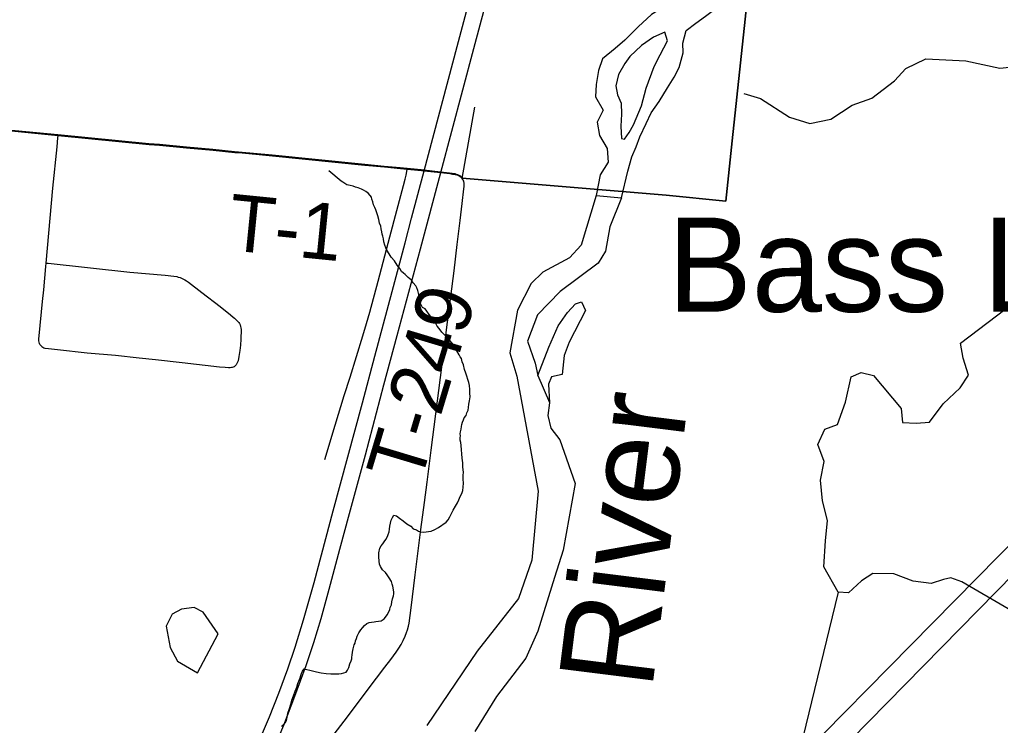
# Model space of a CAD drawing. Extents: x 0 to 34, y 0 to 22.
# Drawn here: x 23.47 to 24.456, y 18.35 to 19.059 of the extents above; entities that cross this region are included whole.
import ezdxf

# ---------------------------------------------------------------- set-up
doc = ezdxf.new("R2010")
doc.units = 0
for name, color, linetype in [('GM_X_City_Street', 7, 'Continuous'), ('GM_X_Major_River', 7, 'Continuous'), ('GM_X_Major_River_Text', 7, 'Continuous'), ('GM_X_Minor_Lake', 7, 'Continuous'), ('GM_X_Minor_Lake_Text', 7, 'Continuous'), ('GM_X_Minor_River', 7, 'Continuous'), ('GM_X_Rail_Line', 7, 'Continuous'), ('GM_X_State_Route', 7, 'Continuous'), ('GM_X_Township_Road', 7, 'Continuous'), ('GM_X_Township_Road_Text', 7, 'Continuous'), ('SH_Border', 7, 'Continuous'), ('SH_Data', 7, 'Continuous')]:
    doc.layers.add(name, color=color, linetype=linetype)

msp = doc.modelspace()

# ---------------------------------------------------------------- linework, layer by layer
at = {"layer": 'GM_X_City_Street'}
msp.add_line((23.91525, 18.89961), (23.92788, 18.97126), dxfattribs=at)
at = {"layer": 'GM_X_Major_River'}
for points in [[(24.04974, 18.88251), (24.03472, 18.83263), (24.02303, 18.82006), (23.99611, 18.80561), (23.98444, 18.79417), (23.97086, 18.76724), (23.96295, 18.7246), (23.96992, 18.7009), (23.99162, 18.5854), (23.9853, 18.51617), (23.97179, 18.47747), (23.93024, 18.42473), (23.87979, 18.34985)], [(24.07532, 18.88014), (24.06364, 18.85119), (24.05922, 18.82666), (24.05171, 18.81473), (24.01344, 18.78619), (23.99084, 18.76253), (23.98069, 18.73625), (23.98846, 18.71405), (23.99118, 18.70184)], [(23.99118, 18.70184), (24.00235, 18.73008), (24.0115, 18.75154), (24.02088, 18.76502), (24.02901, 18.77358), (24.03513, 18.77573), (24.03912, 18.76692), (24.02256, 18.73536), (24.01774, 18.72179), (24.01546, 18.70285), (24.00479, 18.70042), (24.00198, 18.69288), (24.00299, 18.67422)], [(23.99118, 18.70184), (24.00298, 18.67441)], [(24.00299, 18.67422), (24.00115, 18.66137), (24.00424, 18.64877), (24.01342, 18.63715), (24.0286, 18.59313), (24.01665, 18.52632), (24.00799, 18.49887), (23.99105, 18.44471), (23.97899, 18.41773), (23.94955, 18.37907), (23.9278, 18.344)]]:
    msp.add_lwpolyline(points, dxfattribs=at)
at = {"layer": 'GM_X_Minor_Lake'}
msp.add_line((24.04974, 18.88251), (24.07532, 18.88014), dxfattribs=at)
for points in [[(24.21066, 19.11999), (24.18129, 19.11454), (24.17012, 19.10598), (24.15542, 19.09025), (24.1435, 19.0817), (24.1301, 19.07583), (24.11748, 19.07186), (24.1052, 19.06445), (24.09207, 19.05212), (24.07855, 19.03865), (24.06891, 19.03044), (24.0562, 19.02), (24.05222, 19.00828), (24.04972, 18.99425), (24.04914, 18.98171), (24.05692, 18.96827), (24.05065, 18.95621), (24.05311, 18.94286), (24.06089, 18.9298), (24.06182, 18.9161), (24.05364, 18.9033), (24.04974, 18.88251)], [(24.07532, 18.88014), (24.08146, 18.90703), (24.08549, 18.92142), (24.08983, 18.93161), (24.09378, 18.94144), (24.10008, 18.95502), (24.10519, 18.96559), (24.11297, 18.97687), (24.12156, 18.9908), (24.12818, 19.00134), (24.13328, 19.01114), (24.13731, 19.0259), (24.13671, 19.0358), (24.14032, 19.04829), (24.14995, 19.05574), (24.15957, 19.06281), (24.17149, 19.07136), (24.18264, 19.07878), (24.20853, 19.09682)], [(24.11862, 19.04674), (24.10751, 19.0416), (24.09521, 19.03343), (24.08362, 19.02222), (24.07857, 19.01507), (24.07231, 19.00415), (24.06947, 18.99279), (24.07123, 18.98363), (24.07491, 18.97521), (24.07512, 18.96417), (24.07455, 18.9524), (24.07512, 18.93984), (24.07815, 18.93903), (24.08282, 18.9458), (24.08713, 18.95371)], [(24.08713, 18.95371), (24.09541, 18.97259), (24.09987, 18.99039), (24.10819, 19.01231), (24.11408, 19.024), (24.12152, 19.03795), (24.11862, 19.04674)], [(24.46368, 18.46736), (24.41719, 18.49451), (24.40627, 18.49853), (24.39865, 18.49679), (24.38643, 18.49286), (24.36826, 18.49513), (24.34868, 18.50237), (24.32783, 18.50279), (24.3163, 18.49543), (24.30316, 18.48317), (24.29293, 18.48414), (24.27865, 18.5095), (24.28031, 18.53566), (24.28224, 18.55613), (24.27732, 18.5756), (24.27508, 18.59653), (24.27887, 18.61543), (24.27238, 18.63228), (24.27952, 18.6477), (24.29213, 18.65238), (24.30017, 18.675), (24.30599, 18.70032), (24.31594, 18.70467), (24.3284, 18.70175), (24.35618, 18.66853), (24.35742, 18.65446), (24.37144, 18.65379), (24.38474, 18.65466), (24.39839, 18.67337), (24.4154, 18.68935), (24.424, 18.70208), (24.41866, 18.71927), (24.41592, 18.73414), (24.47024, 18.77555)], [(23.66996, 18.44224), (23.65484, 18.46382), (23.64583, 18.46857), (23.63328, 18.46693), (23.62369, 18.46181), (23.61776, 18.44978), (23.62189, 18.42842), (23.6292, 18.4146), (23.64907, 18.4028)], [(23.64907, 18.4028), (23.66996, 18.44224)]]:
    msp.add_lwpolyline(points, dxfattribs=at)
at = {"layer": 'GM_X_Minor_River'}
for points in [[(24.19821, 18.98522), (24.21486, 18.98011), (24.24407, 18.96128), (24.26442, 18.95479), (24.28538, 18.9593), (24.3069, 18.97328), (24.32677, 18.98047), (24.3495, 18.99785), (24.36075, 19.01014), (24.38105, 19.01998), (24.42122, 19.01802), (24.45521, 19.01049), (24.48753, 19.01401), (24.51779, 19.02895), (24.59677, 19.0896), (24.6617, 19.13042), (24.68619, 19.14093), (24.69885, 19.14788), (24.75657, 19.16986), (24.77115, 19.1783)], [(23.83614, 18.8389), (23.83542, 18.84157), (23.8347, 18.84386), (23.83436, 18.84615), (23.83365, 18.8492), (23.83331, 18.85186), (23.83222, 18.85492), (23.83151, 18.85835), (23.83043, 18.86217), (23.82934, 18.86522), (23.82825, 18.86828), (23.82753, 18.87057), (23.82605, 18.87326), (23.82534, 18.87631), (23.82425, 18.87899), (23.8239, 18.88089), (23.82092, 18.88474), (23.81829, 18.88668), (23.81604, 18.88786), (23.81416, 18.88903), (23.81076, 18.89023), (23.80811, 18.89103), (23.80547, 18.89183), (23.80245, 18.89264), (23.79942, 18.89345), (23.79716, 18.89463), (23.79528, 18.8958), (23.7934, 18.89697), (23.78119, 18.90739)], [(23.87664, 18.54417), (23.87893, 18.54452), (23.88121, 18.54486), (23.88387, 18.5452), (23.8877, 18.54703), (23.89152, 18.54887), (23.89921, 18.55444), (23.90114, 18.55669), (23.90271, 18.5597), (23.90428, 18.5631), (23.90623, 18.56648), (23.90857, 18.57024), (23.91052, 18.57363), (23.9117, 18.57665), (23.91328, 18.58004), (23.91445, 18.5823), (23.91524, 18.58419), (23.91565, 18.58608), (23.91608, 18.5895), (23.91653, 18.59367), (23.91621, 18.59747), (23.91627, 18.60127), (23.91633, 18.60469), (23.91598, 18.60697), (23.91565, 18.61002), (23.91571, 18.61382), (23.91503, 18.61877), (23.91472, 18.62295), (23.9144, 18.62714), (23.91409, 18.63132), (23.91376, 18.63436), (23.91304, 18.63666), (23.91307, 18.63894), (23.91349, 18.64121), (23.91314, 18.64311), (23.91355, 18.64501), (23.91397, 18.64766), (23.91439, 18.65031), (23.91481, 18.65258), (23.9156, 18.65485), (23.9164, 18.65712), (23.91719, 18.659), (23.91913, 18.66163), (23.91993, 18.66428), (23.92111, 18.66692), (23.92153, 18.66957), (23.92196, 18.67298), (23.9224, 18.67639), (23.92322, 18.68018), (23.9229, 18.68398), (23.92296, 18.68778), (23.92264, 18.69159), (23.92193, 18.69464), (23.91866, 18.70419), (23.91758, 18.70763), (23.91652, 18.71258), (23.91504, 18.71527), (23.91433, 18.7187), (23.91323, 18.72061), (23.91212, 18.72253), (23.9099, 18.72637), (23.90841, 18.72829), (23.90694, 18.73136), (23.90509, 18.73405), (23.90285, 18.73674), (23.90061, 18.73906), (23.898, 18.74176), (23.89651, 18.74368), (23.89464, 18.74524), (23.89204, 18.74908), (23.89018, 18.75139), (23.88833, 18.75446), (23.88647, 18.75715), (23.88424, 18.75985), (23.88201, 18.76292), (23.87979, 18.76638), (23.87792, 18.76869), (23.87529, 18.76987), (23.87381, 18.77255), (23.87308, 18.77447), (23.87235, 18.77638), (23.87202, 18.77942), (23.8717, 18.78323), (23.87062, 18.78704), (23.86953, 18.78972), (23.86842, 18.79164), (23.86581, 18.79472), (23.86433, 18.7974), (23.86096, 18.80012), (23.85797, 18.80321), (23.85609, 18.80438), (23.85422, 18.80631), (23.85237, 18.80938), (23.84977, 18.81246), (23.84718, 18.81706), (23.84382, 18.82054), (23.83901, 18.82822), (23.83828, 18.83013), (23.83756, 18.8328), (23.83647, 18.83585), (23.83614, 18.8389)], [(23.73539, 18.35044), (23.73771, 18.35307), (23.7385, 18.35495), (23.73931, 18.35836), (23.74014, 18.36253), (23.74172, 18.36706), (23.74294, 18.3716), (23.74414, 18.37538), (23.74572, 18.37991), (23.74732, 18.38445), (23.7489, 18.3886), (23.7501, 18.39238), (23.75168, 18.39615), (23.75247, 18.39804), (23.75288, 18.40031), (23.75367, 18.4022), (23.75485, 18.40446), (23.75641, 18.4071), (23.76473, 18.40506), (23.76888, 18.40385), (23.77343, 18.40301), (23.77835, 18.40217), (23.78328, 18.40209), (23.78745, 18.40202), (23.79125, 18.40196), (23.79391, 18.4023), (23.7962, 18.40302), (23.79849, 18.40374), (23.80004, 18.40561), (23.80122, 18.40825), (23.80242, 18.41203), (23.80361, 18.41505), (23.8044, 18.41694), (23.80443, 18.41884), (23.80446, 18.42074), (23.80488, 18.42377), (23.8057, 18.42718), (23.80652, 18.43096), (23.80768, 18.43285), (23.8081, 18.43512), (23.8089, 18.43739), (23.80969, 18.43965), (23.81126, 18.44305), (23.81321, 18.44605), (23.81514, 18.4483), (23.81708, 18.45055), (23.81938, 18.45241), (23.82168, 18.45351), (23.82396, 18.45385), (23.82662, 18.45419), (23.82853, 18.45454), (23.83119, 18.45488), (23.83385, 18.45521), (23.83692, 18.45706), (23.83809, 18.45894), (23.83964, 18.4612), (23.8412, 18.46345), (23.84239, 18.46647), (23.8428, 18.46874), (23.84398, 18.47138), (23.84441, 18.47442), (23.84522, 18.47744), (23.84602, 18.48047), (23.84643, 18.48236), (23.84646, 18.48426), (23.84542, 18.48998), (23.84469, 18.49189), (23.84397, 18.49456), (23.84175, 18.4984), (23.8399, 18.50147), (23.83804, 18.50378), (23.83505, 18.50649), (23.8332, 18.50994), (23.8321, 18.51223), (23.83177, 18.51528), (23.83146, 18.51946), (23.83152, 18.52364), (23.83236, 18.52819), (23.83391, 18.53044), (23.83546, 18.5327), (23.83663, 18.53458), (23.83857, 18.53682), (23.84013, 18.53984), (23.84093, 18.5421), (23.84173, 18.54475), (23.84215, 18.5474), (23.84258, 18.55044), (23.84301, 18.55347), (23.84381, 18.5565), (23.84499, 18.55914), (23.84655, 18.56139), (23.84919, 18.56059), (23.85219, 18.55826), (23.85594, 18.55553), (23.8597, 18.55281), (23.86346, 18.55047), (23.86607, 18.54777), (23.86909, 18.54658), (23.87135, 18.5454), (23.87323, 18.54461), (23.87664, 18.54417)], [(24.25476, 18.32571), (24.29312, 18.48412)], [(23.73347, 18.34934), (23.73539, 18.35044)]]:
    msp.add_lwpolyline(points, dxfattribs=at)
at = {"layer": 'GM_X_Rail_Line'}
for points in [[(22.51637, 16.93545), (22.62022, 16.9977), (23.2863, 17.39264), (23.9265, 17.98458), (25.28936, 19.3687), (25.68844, 19.73766)], [(22.51637, 16.40146), (22.60404, 16.47321), (22.68043, 16.53593), (22.99636, 16.90708), (23.39125, 17.4049), (25.21918, 19.26631), (25.71658, 19.73499)]]:
    msp.add_lwpolyline(points, dxfattribs=at)
at = {"layer": 'GM_X_State_Route'}
for points in [[(23.87686, 18.90747), (23.9102, 19.03214), (23.93685, 19.13298), (23.94595, 19.16758), (23.95368, 19.20328), (23.9655, 19.27351), (23.98254, 19.39848), (23.98329, 19.40396), (23.98824, 19.44081), (23.99745, 19.51056), (24.00239, 19.54954), (24.00346, 19.55877), (24.01399, 19.63739), (24.02402, 19.71586), (24.03768, 19.81818), (24.04574, 19.88184), (24.05384, 19.95159), (24.06336, 20.04297), (24.07685, 20.16092), (24.08815, 20.26181)], [(23.89359, 18.90561), (23.92693, 19.03029), (23.94816, 19.11059)], [(23.71164, 18.33518), (23.72146, 18.35871), (23.73086, 18.3824), (23.73991, 18.4069), (23.74726, 18.4287), (23.75571, 18.45603), (23.76629, 18.49373), (23.78565, 18.56573), (23.81494, 18.6743), (23.82747, 18.72112), (23.84469, 18.78596), (23.85793, 18.83513), (23.86436, 18.85978), (23.87686, 18.90747)], [(23.72663, 18.32812), (23.73595, 18.35045), (23.74713, 18.37939), (23.75834, 18.41033), (23.76601, 18.43328), (23.7734, 18.45762), (23.78151, 18.48695), (23.79222, 18.52717), (23.80183, 18.5632), (23.81786, 18.62192), (23.83633, 18.69223), (23.84972, 18.74203), (23.87323, 18.82895), (23.89359, 18.90561)]]:
    msp.add_lwpolyline(points, dxfattribs=at)
at = {"layer": 'GM_X_Township_Road'}
for p, q in [((23.66489, 18.92811), (23.68657, 18.92591)), ((23.87686, 18.90747), (23.89359, 18.90561))]:
    msp.add_line(p, q, dxfattribs=at)
for points in [[(23.2393, 18.97041), (23.24518, 18.96983), (23.26684, 18.96742), (23.32116, 18.96199), (23.38034, 18.95539), (23.4555, 18.9481), (23.5092, 18.94295)], [(23.49727, 18.81468), (23.50393, 18.88981), (23.50821, 18.93145), (23.509, 18.94063), (23.5092, 18.94295)], [(23.5092, 18.94295), (23.6007, 18.93395), (23.61117, 18.93313), (23.63832, 18.9306), (23.66489, 18.92811)], [(23.68657, 18.92591), (23.69076, 18.92561), (23.72442, 18.9224), (23.81751, 18.91321), (23.8371, 18.91124), (23.85318, 18.90975), (23.86003, 18.9091)], [(23.77708, 18.61746), (23.78759, 18.65188), (23.7967, 18.68155), (23.80244, 18.70007), (23.81522, 18.74166), (23.81894, 18.75409), (23.82223, 18.76548), (23.83064, 18.79661), (23.84247, 18.84099), (23.84956, 18.86735), (23.85632, 18.89268), (23.85803, 18.89895), (23.85893, 18.90291), (23.85967, 18.90682), (23.86003, 18.9091)], [(23.86003, 18.9091), (23.87423, 18.90775), (23.87686, 18.90747)], [(23.89359, 18.90561), (23.90275, 18.90458), (23.90548, 18.90413), (23.90817, 18.90366), (23.90972, 18.90329), (23.91101, 18.90287), (23.91222, 18.90228), (23.91306, 18.90177), (23.91399, 18.90107), (23.91462, 18.90034), (23.91525, 18.89961)], [(23.7774, 18.32972), (23.79988, 18.35883), (23.82081, 18.38644), (23.83743, 18.40847), (23.8434, 18.41626), (23.84881, 18.4236), (23.85151, 18.42775), (23.85373, 18.43139), (23.85588, 18.43548), (23.85792, 18.4399), (23.85931, 18.44343), (23.86013, 18.44609), (23.86113, 18.44984), (23.86179, 18.45288), (23.86383, 18.46818), (23.86803, 18.50153), (23.87367, 18.54707), (23.87713, 18.57419), (23.87983, 18.59449), (23.88392, 18.62653), (23.89331, 18.69974), (23.90044, 18.75516), (23.90702, 18.80693), (23.91012, 18.83339), (23.91307, 18.85736), (23.9151, 18.87459), (23.91676, 18.8894), (23.91698, 18.89172), (23.91708, 18.89304), (23.9171, 18.89453), (23.91704, 18.89529), (23.91693, 18.89611), (23.91668, 18.89695), (23.91623, 18.89804), (23.91581, 18.89877), (23.91525, 18.89961)], [(23.49091, 18.73298), (23.49049, 18.73392), (23.49016, 18.73508), (23.48996, 18.7364), (23.48989, 18.73739), (23.48995, 18.7385), (23.49015, 18.74153), (23.49355, 18.77613), (23.49469, 18.78786), (23.49696, 18.81133), (23.49727, 18.81468)], [(23.49727, 18.81468), (23.49928, 18.81442), (23.58116, 18.80564), (23.61682, 18.8024), (23.62533, 18.80152), (23.62829, 18.80101), (23.62981, 18.80064), (23.6317, 18.80007), (23.63378, 18.79919), (23.63649, 18.7978), (23.63832, 18.79672), (23.64015, 18.79553), (23.65369, 18.78515), (23.67212, 18.77112), (23.6824, 18.76269), (23.68516, 18.76038), (23.68651, 18.75926), (23.68781, 18.75807), (23.69019, 18.75571), (23.6908, 18.75485), (23.69135, 18.75396), (23.69201, 18.75256), (23.69248, 18.75102), (23.69281, 18.74967), (23.693, 18.74797), (23.69269, 18.73807), (23.69228, 18.73225), (23.69177, 18.72676), (23.69088, 18.72068), (23.68996, 18.71658), (23.68941, 18.71511), (23.68883, 18.71388), (23.68842, 18.71311), (23.68802, 18.71253), (23.68754, 18.71186), (23.68709, 18.71137)], [(23.49091, 18.73298), (23.4915, 18.73203), (23.49211, 18.73143), (23.49295, 18.73072), (23.49387, 18.73013), (23.49492, 18.7296), (23.4957, 18.72931), (23.49633, 18.72918), (23.49947, 18.72875), (23.50862, 18.72786), (23.53825, 18.72452), (23.56693, 18.72202), (23.59045, 18.71957), (23.60698, 18.71782), (23.63377, 18.71491), (23.67121, 18.71055), (23.67695, 18.71003), (23.68049, 18.70984), (23.68214, 18.70984), (23.68337, 18.70996), (23.68452, 18.71014), (23.68549, 18.71048), (23.68631, 18.71089), (23.68709, 18.71137)]]:
    msp.add_lwpolyline(points, dxfattribs=at)
at = {"layer": 'SH_Border'}
for points in [[(24.23308, 19.37359), (24.18638, 18.93741), (24.17995, 18.87699), (24.12014, 18.88296), (23.91502, 18.90014), (23.91439, 18.90087), (23.91376, 18.9016), (23.91283, 18.90231), (23.91199, 18.90281), (23.91078, 18.9034), (23.90949, 18.90382), (23.90794, 18.90419), (23.90525, 18.90467), (23.90252, 18.90512), (23.89336, 18.90615), (23.87663, 18.908), (23.87399, 18.90828), (23.8598, 18.90963), (23.85295, 18.91028), (23.83687, 18.91178), (23.81728, 18.91375), (23.72419, 18.92294), (23.69053, 18.92614), (23.68634, 18.92644), (23.66466, 18.92864), (23.63809, 18.93113), (23.61094, 18.93367), (23.60047, 18.93449), (23.50897, 18.94348), (23.45527, 18.94863)], [(23.45527, 18.94863), (23.50897, 18.94348), (23.60047, 18.93449), (23.61094, 18.93367), (23.63809, 18.93113), (23.66466, 18.92864), (23.68634, 18.92644), (23.69053, 18.92614), (23.72419, 18.92294), (23.81728, 18.91375), (23.83687, 18.91178), (23.85295, 18.91028), (23.8598, 18.90963), (23.87399, 18.90828), (23.87663, 18.908), (23.89336, 18.90615), (23.90252, 18.90512), (23.90525, 18.90467), (23.90794, 18.90419), (23.90949, 18.90382), (23.91078, 18.9034), (23.91199, 18.90281), (23.91283, 18.90231), (23.91376, 18.9016), (23.91439, 18.90087), (23.91502, 18.90014), (24.12014, 18.88296), (24.17995, 18.87699), (24.18638, 18.93741), (24.23308, 19.37359)]]:
    msp.add_lwpolyline(points, dxfattribs=at)
at = {"layer": 'SH_Data'}
for points in [[(23.45527, 18.94863), (23.50897, 18.94348), (23.60047, 18.93449), (23.61094, 18.93367), (23.63809, 18.93113), (23.66466, 18.92864), (23.68634, 18.92644), (23.69053, 18.92614), (23.72419, 18.92294), (23.81728, 18.91375), (23.83687, 18.91178), (23.85295, 18.91028), (23.8598, 18.90963), (23.87399, 18.90828), (23.87663, 18.908), (23.89336, 18.90615), (23.90252, 18.90512), (23.90525, 18.90467), (23.90794, 18.90419), (23.90949, 18.90382), (23.91078, 18.9034), (23.91199, 18.90281), (23.91283, 18.90231), (23.91376, 18.9016), (23.91439, 18.90087), (23.91502, 18.90014), (24.12014, 18.88296), (24.17995, 18.87699), (24.18638, 18.93741), (24.23308, 19.37359)], [(24.23308, 19.37359), (24.18638, 18.93741), (24.17995, 18.87699), (24.12014, 18.88296), (23.91502, 18.90014), (23.91439, 18.90087), (23.91376, 18.9016), (23.91283, 18.90231), (23.91199, 18.90281), (23.91078, 18.9034), (23.90949, 18.90382), (23.90794, 18.90419), (23.90525, 18.90467), (23.90252, 18.90512), (23.89336, 18.90615), (23.87663, 18.908), (23.87399, 18.90828), (23.8598, 18.90963), (23.85295, 18.91028), (23.83687, 18.91178), (23.81728, 18.91375), (23.72419, 18.92294), (23.69053, 18.92614), (23.68634, 18.92644), (23.66466, 18.92864), (23.63809, 18.93113), (23.61094, 18.93367), (23.60047, 18.93449), (23.50897, 18.94348), (23.45527, 18.94863)]]:
    msp.add_lwpolyline(points, dxfattribs=at)

# ---------------------------------------------------------------- texts
at = {"layer": 'GM_X_Major_River_Text'}
msp.add_text('River', height=0.094711, rotation=82.88733, dxfattribs=at).set_placement((24.10585, 18.38494))
at = {"layer": 'GM_X_Minor_Lake_Text'}
msp.add_text('Bass Lake', height=0.094695, rotation=359.99463, dxfattribs=at).set_placement((24.12168, 18.76574))
at = {"layer": 'GM_X_Township_Road_Text'}
for s, rotation, p in [('T-1', 354.28896, (23.67835, 18.82784)), ('T-249', 73.24715, (23.87256, 18.59077))]:
    msp.add_text(s, height=0.056818, rotation=rotation, dxfattribs=at).set_placement(p)

doc.saveas('drawing.dxf')
